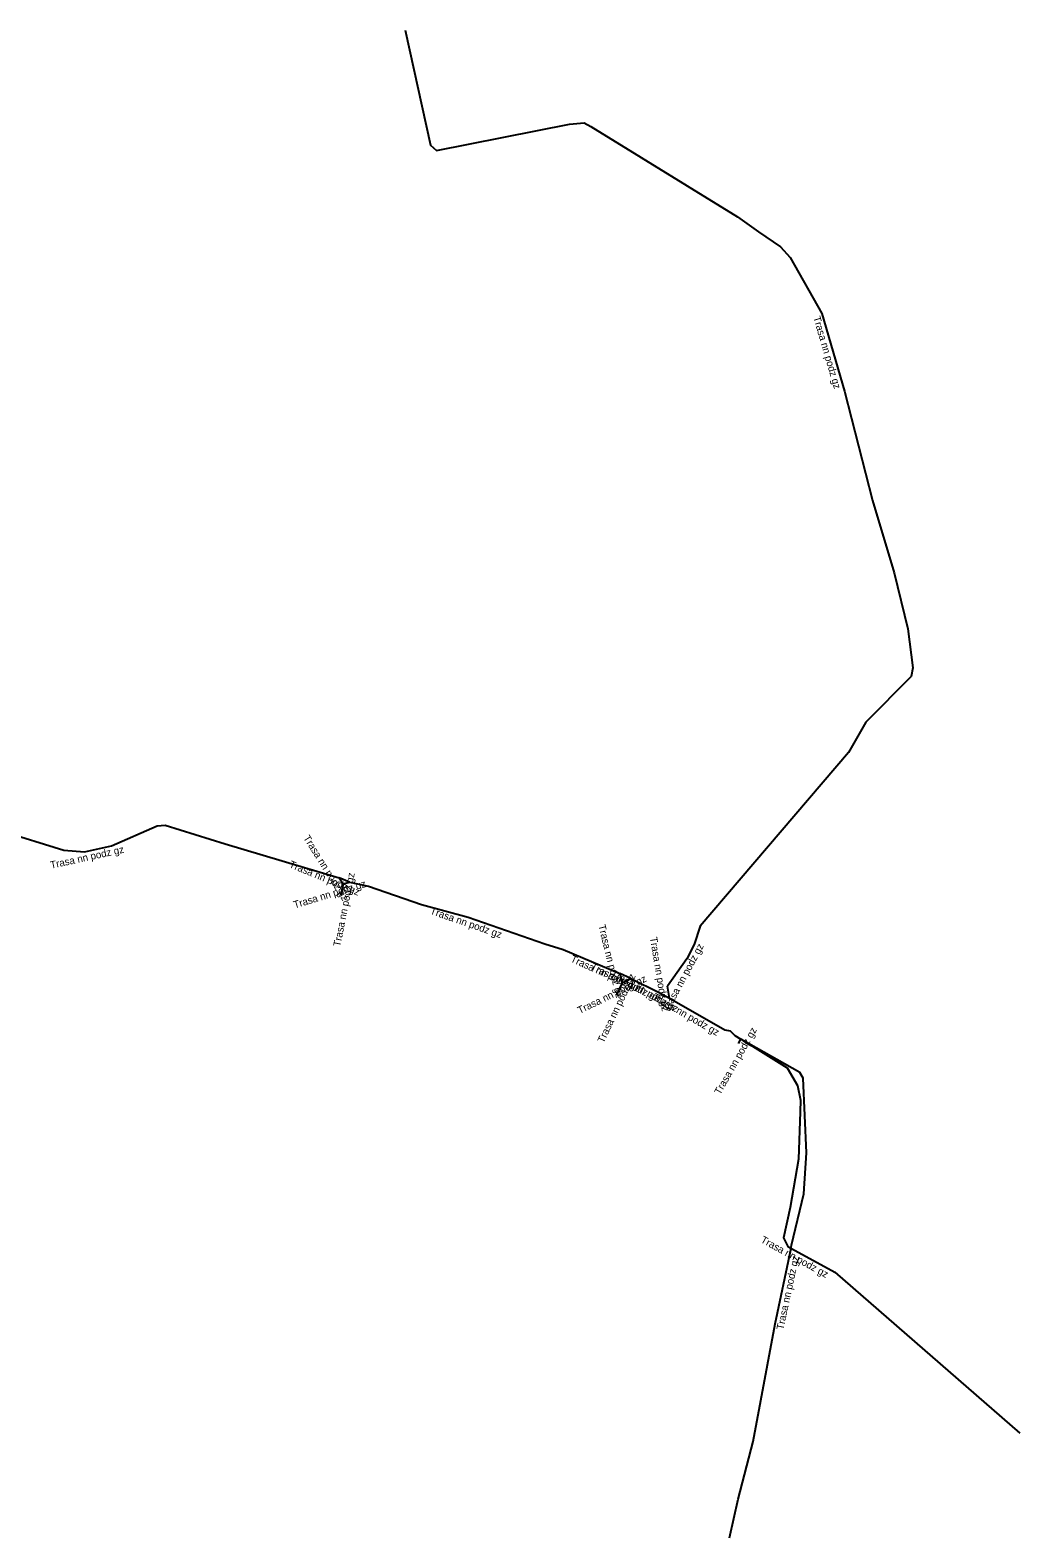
# Model space of a CAD drawing. Extents: x -743572 to -742920, y -1027115 to -1026442.
# Drawn here: x -742988.4 to -742920.4, y -1026799.1 to -1026695.4 of the extents above; entities that cross this region are included whole.
import ezdxf

# ---------------------------------------------------------------- set-up
doc = ezdxf.new("R2010")
doc.units = 0
doc.layers.add('Popiskový text - Ostatní atributy Trasy', color=7, linetype='Continuous')
doc.layers.add('Spojnice NN', color=7, linetype='Continuous')

msp = doc.modelspace()

# ---------------------------------------------------------------- linework, layer by layer
at = {"layer": 'Spojnice NN'}
for points in [[(-742962.61, -1026695.43), (-742960.87, -1026703.33), (-742960.45, -1026703.7), (-742951.32, -1026701.88), (-742950.31, -1026701.8), (-742949.84, -1026702.04), (-742939.78, -1026708.26), (-742938.33, -1026709.28), (-742936.82, -1026710.33), (-742936.16, -1026711.05), (-742933.97, -1026714.91), (-742932.41, -1026720.23), (-742930.49, -1026727.76), (-742929.01, -1026732.73), (-742928.06, -1026736.58), (-742927.71, -1026739.26), (-742927.83, -1026739.85), (-742930.96, -1026743), (-742932.14, -1026745.08), (-742942.33, -1026757.01)], [(-742999.36, -1026747.54), (-742998.56, -1026747.3), (-742997.4, -1026747.76), (-742994.65, -1026749.14), (-742986.06, -1026751.78), (-742984.65, -1026751.9), (-742982.79, -1026751.49), (-742979.65, -1026750.12), (-742979.1, -1026750.07), (-742974.97, -1026751.36), (-742967.14, -1026753.69)], [(-742966.44, -1026753.98), (-742967.14, -1026753.69)], [(-742967.14, -1026753.69), (-742966.88, -1026754.11)], [(-742966.88, -1026754.11), (-742967.03, -1026754.89)], [(-742966.88, -1026754.11), (-742966.44, -1026753.98)], [(-742966.44, -1026753.98), (-742965.13, -1026754.26), (-742961.48, -1026755.52), (-742958.29, -1026756.39), (-742953.01, -1026758.22), (-742951.76, -1026758.62), (-742947.85, -1026760.28)], [(-742942.33, -1026757.01), (-742942.75, -1026758.28), (-742943.26, -1026759.25), (-742944.59, -1026761.13)], [(-742947.7, -1026760.91), (-742948.06, -1026761.68)], [(-742947.85, -1026760.28), (-742947.7, -1026760.91)], [(-742947.09, -1026760.62), (-742947.85, -1026760.28)], [(-742947.7, -1026760.91), (-742947.09, -1026760.62)], [(-742947.09, -1026760.62), (-742945.15, -1026761.57)], [(-742945.15, -1026761.57), (-742944.45, -1026761.96)], [(-742944.45, -1026761.96), (-742944.59, -1026761.13)], [(-742944.45, -1026761.96), (-742940.63, -1026764.14), (-742940.28, -1026764.21), (-742939.95, -1026764.53), (-742939.53, -1026764.78)], [(-742940.33, -1026799.06), (-742939.72, -1026796.39), (-742938.7, -1026792.44), (-742937.18, -1026784.35), (-742936.1, -1026779.26), (-742936.06, -1026778.95), (-742935.2, -1026775.41), (-742935.02, -1026772.59), (-742935.25, -1026767.46), (-742935.49, -1026767.07), (-742939.53, -1026764.78)], [(-742939.7, -1026765.08), (-742939.53, -1026764.78)], [(-742939.53, -1026764.78), (-742939.23, -1026765.01), (-742938.74, -1026765.26), (-742936.36, -1026766.76), (-742935.65, -1026767.97), (-742935.43, -1026768.97), (-742935.46, -1026769.77), (-742935.57, -1026773.04), (-742936.15, -1026776.35), (-742936.61, -1026778.44), (-742936.3, -1026779.04), (-742933.08, -1026780.8), (-742920.36, -1026791.86)]]:
    msp.add_lwpolyline(points, dxfattribs=at)

# ---------------------------------------------------------------- texts
at = {"layer": 'Popiskový text - Ostatní atributy Trasy'}
for rotation, p in [(286.3102, (-742934.57, -1026715.17)), (302.0662, (-742969.63, -1026750.95)), (12.4174, (-742986.94, -1026753.07)), (337.4845, (-742970.63, -1026752.95)), (78.8323, (-742967.07, -1026758.45)), (16.8074, (-742970.2, -1026755.8)), (340.9065, (-742960.94, -1026756.16)), (283.8665, (-742949.34, -1026756.97)), (279.2712, (-742945.79, -1026757.8)), (335.7157, (-742951.29, -1026759.44)), (61.8659, (-742944.5, -1026762.93)), (334.0622, (-742949.91, -1026759.97)), (330.6933, (-742948.51, -1026760.42)), (26.0672, (-742950.61, -1026763.06)), (64.5193, (-742948.97, -1026765.09)), (330.2108, (-742945.68, -1026762.01)), (60.4993, (-742940.96, -1026768.64)), (331.2027, (-742938.22, -1026778.72)), (78.0513, (-742936.61, -1026784.79))]:
    msp.add_text('Trasa nn podz gz', height=0.5, rotation=rotation, dxfattribs=at).set_placement(p)

doc.saveas('drawing.dxf')
